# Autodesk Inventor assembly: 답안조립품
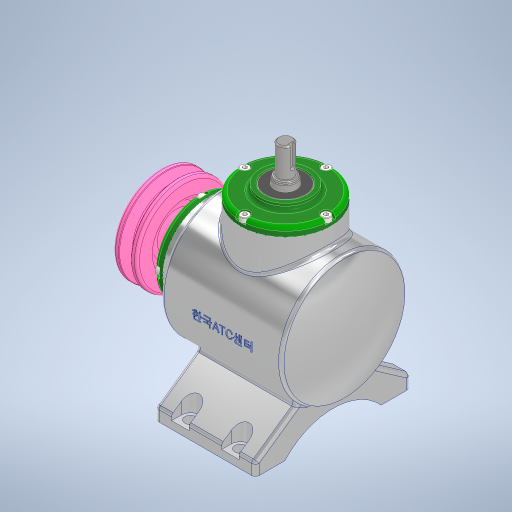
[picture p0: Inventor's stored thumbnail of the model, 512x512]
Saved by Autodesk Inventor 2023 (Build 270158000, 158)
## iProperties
Created: 2023-12
Part Number: 답안조립품
Document SubType Name: Assembly
Designer: asung
Author: asung
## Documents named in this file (17)
- C:\Users\asung\Desktop\731210v1001\답안조립품.iam
- C:\Users\asung\Desktop\731210v1001\본체.ipt
- C:\Users\asung\Desktop\731210v1001\731210V1001\V-벨트풀리.ipt
- C:\Users\asung\Desktop\731210v1001\731210V1001\메인 베벨기어.ipt
- C:\Users\asung\Desktop\731210v1001\731210V1001\메인 축.ipt
- 메인 축.ipt
- C:\Users\asung\Desktop\731210v1001\731210V1001\베어링 6203.ipt
- C:\Users\asung\Desktop\731210v1001\731210V1001\볼트 M4 x 10.ipt
- C:\Users\asung\Desktop\731210v1001\731210V1001\서브 베벨기어.ipt
- C:\Users\asung\Desktop\731210v1001\731210V1001\서브 축.ipt
- 서브 축.ipt
- C:\Users\asung\Desktop\731210v1001\731210V1001\오일실 17 x 32 x 8.ipt
- C:\Users\asung\Desktop\731210v1001\731210V1001\와셔 4 x 16.ipt
- C:\Users\asung\Desktop\731210v1001\731210V1001\커버.ipt
- C:\Users\asung\Desktop\731210v1001\731210V1001\키 4 x 4 x 14.ipt
- C:\Users\asung\Desktop\731210v1001\731210V1001\키 5 x 5 x 14.ipt
- C:\Users\asung\Desktop\731210v1001\731210V1001\육각볼트 M4 x 8.ipt
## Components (1 placed, 1 different names)
1. V-벨트풀리:1
